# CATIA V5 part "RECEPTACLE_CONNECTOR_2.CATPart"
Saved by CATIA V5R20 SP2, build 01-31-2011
Part number: RECEPTACLE_CONNECTOR_2
Revision: ---
Publications: "MasterKeywayAxis", "InsertFrontFace", "InsertRearFace", "Logical Termination.1", "Logical Pin.1", "CCP", "Face_generated(CCP)", "Face_generated(CCP).1", "BCP", "BCPRPoint_generated(BCP)", "BCPPlane_generated(BCP)", "CaCP", "Face_generated(CaCP)", "Face_generated(CaCP).1", "BaCP", "Face_generated(BaCP)", "Face_generated(BaCP).1", "Axis_generated(CaCP)", "Axis_generated(BaCP)", "Axis_generated(CCP)"
Bounding box of the stored display mesh (mm): x 0 to 34.925, y -14.288 to 14.288, z -14.288 to 14.288
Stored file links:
  C:\Users\ajc8720\Documents\BOEING_WORK\0001-2CES\004-AP242\Boeing-Generic_Harness_R3\RECEPTACLE_CONNECTOR_2.CATPart
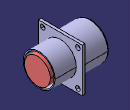
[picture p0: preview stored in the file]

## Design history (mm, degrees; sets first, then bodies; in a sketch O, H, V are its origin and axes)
Parameters
  PartNumber = "RECEPTACLE_CONNECTOR_2"
AxisSystem1 "MasterKeywayAxis": origin (0, 0, 0), X (1, 0, 0), Y (0, 1, 0), Z (0, 0, 1)
Set1 "EGF"
  Set2 "BCP"
    Plane1 "BCPPlane": type Offset, RefPlane face of Pad5, Offset 0, reversed
    Point1 "BCPRPoint": type OnPlane, Support Plane1, H 0, V 0, Direction (0, 1, 0)
  Set3 "BaCP"
    Point2 "BaCPRPoint": (36.0934 {= deleted_ShellLength}, 0, 0)
    Plane2: type OffsetPt, RefPlane yz-plane, RefPoint Point2
  Set4 "CCP"
    Point3 "CCPRPoint": (0, 0, 0)
    Plane3: type OffsetPt, RefPlane yz-plane, RefPoint Point3
  Set5 "CaCP"
    Point4 "CaCPRPoint": type Center, Curve edge [face of Pad1 | face of Pad3]
    Plane4: type OffsetPt, RefPlane yz-plane, RefPoint Point4
Body1 "Shell" (main body)
  Sketch1 on yz-plane, origin (0, 0, 0), H (0, 1, 0), V (0, 0, 1)
    circle A1 centre (0, 0) radius 11.8745
    radius A1 = 11.8745
  Pad1 "ShellFront": profile Sketch1, direction (1, 0, 0), length 18.2372 {= deleted_FlangeFront}
  Sketch2 on zx-plane, origin (0, 0, 0), H (-1, 0, 0), V (0, 0, 1)
    line L1 (0, 11.4046) -> (-0.7874, 11.4046)
    point P2 (-0.7874, 11.4046)
    line L2 (-0.7874, 11.4046) -> (-0.7874, 11.4046)
    line L3 (-0.7874, 11.8745) -> (0, 11.8745)
    line L4 (0, 11.8745) -> (0, 11.4046)
    line L5 (-0.7874, 11.8745) -> (-0.7874, 11.4046)
    point P6 (-0.7874, 11.4046)
    distance H L1 = 11.4046
    length L1 = 0.7874
    distance L3 H = 11.8745
    horizontal: L1 H, L3 H
    vertical: L2 V, L4 V, L5 V
    coincidence: V L4, L5 P2, P6 P2
  Groove1 "ShellFrontRelief": profile Sketch2, axis Sketch2.H, angle 360
  Sketch3 on face of Pad1, origin (18.2372, 0, 0), H (0, 1, 0), V (0, 0, 1)
    circle A1 centre (0, 0) radius 10.4394
    radius A1 = 10.4394
  Pad2 "ShellRear": profile Sketch3, direction (1, 0, 0), length 17.8562 {= deleted_ShellLength - deleted_FlangeFront}
  Sketch4 on zx-plane, origin (0, 0, 0), H (-1, 0, 0), V (0, 0, 1)
    line L1 (-36.0934, 9.1948) -> (-33.8074, 9.1948)
    line L2 (-33.8074, 9.1948) -> (-33.8074, 10.4394)
    line L3 (-33.8074, 10.4394) -> (-36.0934, 10.4394)
    line L4 (-36.0934, 10.4394) -> (-36.0934, 9.1948)
    length L1 = 2.286
    distance V L4 = 36.0934
    distance H L3 = 10.4394
    distance H L1 = 9.1948
    horizontal: L1 H, L3 H
    vertical: L2 V, L4 V
  Groove2 "ShellRearRelief": profile Sketch4, axis Sketch4.H, angle 360
  Sketch5 on yz-plane, origin (0, 0, 0), H (0, 1, 0), V (0, 0, 1)
    line L1 (-14.2875, -14.2875) -> (14.2875, -14.2875)
    line L2 (14.2875, -14.2875) -> (14.2875, 14.2875)
    line L3 (14.2875, 14.2875) -> (-14.2875, 14.2875)
    line L4 (-14.2875, 14.2875) -> (-14.2875, -14.2875)
    circle A1 centre (0, 0) radius 10.4394
    point P5 (10.3837, 12.6287)
    line L5 (10.3837, 12.6287) -> (10.3837, 12.6287)
    point P6 (10.3837, 12.6287)
    arc A2 centre (11.5062, 11.5062) radius 1.5875 from (10.3837, 12.6287) to (12.6287, 10.3837) cw
    point P7 (11.5062, 11.5062)
    point P8 (12.6287, 10.3837)
    line L6 (12.6287, 10.3837) -> (12.6287, 10.3837)
    point P9 (12.6287, 10.3837)
    arc A3 centre (11.5062, 11.5062) radius 1.5875 from (12.6287, 10.3837) to (10.3837, 12.6287) cw
    point P10 (11.5062, 11.5062)
    construction line L7 (0, 0) -> (16.5549, 16.5549)
    point P12 (12.6287, -10.3837)
    point P13 (12.6287, -10.3837)
    line L8 (12.6287, -10.3837) -> (12.6287, -10.3837)
    point P14 (10.3837, -12.6287)
    arc A4 centre (11.5062, -11.5062) radius 1.5875 from (12.6287, -10.3837) to (10.3837, -12.6287) ccw
    point P16 (10.3837, -12.6287)
    line L9 (10.3837, -12.6287) -> (10.3837, -12.6287)
    arc A5 centre (11.5062, -11.5062) radius 1.5875 from (10.3837, -12.6287) to (12.6287, -10.3837) ccw
    point P18 (-12.6287, -10.3837)
    point P19 (-12.6287, -10.3837)
    line L10 (-12.6287, -10.3837) -> (-12.6287, -10.3837)
    point P20 (-10.3837, -12.6287)
    arc A6 centre (-11.5062, -11.5062) radius 1.5875 from (-12.6287, -10.3837) to (-10.3837, -12.6287) cw
    point P22 (-10.3837, -12.6287)
    line L11 (-10.3837, -12.6287) -> (-10.3837, -12.6287)
    arc A7 centre (-11.5062, -11.5062) radius 1.5875 from (-10.3837, -12.6287) to (-12.6287, -10.3837) cw
    point P24 (-10.3837, 12.6287)
    point P25 (-12.6287, 10.3837)
    arc A8 centre (-11.5062, 11.5062) radius 1.5875 from (-12.6287, 10.3837) to (-10.3837, 12.6287) ccw
    point P27 (-10.3837, 12.6287)
    line L12 (-10.3837, 12.6287) -> (-10.3837, 12.6287)
    point P28 (-12.6287, 10.3837)
    arc A9 centre (-11.5062, 11.5062) radius 1.5875 from (-10.3837, 12.6287) to (-12.6287, 10.3837) ccw
    line L13 (-12.6287, 10.3837) -> (-12.6287, 10.3837)
    radius A1 = 10.4394
    length L2 = 28.575
    length L3 = 28.575
    radius A2 = 1.5875
    distance H P7 = 11.5062
    distance H P10 = 11.5062
    angle H L7 = 45
    horizontal: L1 H, L3 H
    vertical: L2 V, L4 V
    symmetry: L2 L4 V, L3 L1 H, L5 L6 L7, P9 P12 H, P8 P13 H, L6 L8 H, P5 P14 H, A3 A4 H, P6 P16 H, L5 L9 H, A2 A5 H, P12 P18 V, P13 P19 V, L8 L10 V, P14 P20 V, A4 A6 V, P16 P22 V, L9 L11 V, A5 A7 V, P5 P24 V, P9 P25 V, A3 A8 V, P6 P27 V, L5 L12 V, P8 P28 V, A2 A9 V, L6 L13 V
    tangency: A2 L5, L6 A2, A3 L5, A3 L6
    coincidence: P7 L7, P10 L7
    parallelism: L6 L7
  Pad3 "MountingFlange": profile Sketch5, direction (1, 0, 0), length 19.9898 {= deleted_FlangeFront + deleted_FlangeThickness}, opposite side length -18.2372 {= -( deleted_FlangeFront )}
  Sketch6 on yz-plane, origin (0, 0, 0), H (0, 1, 0), V (0, 0, 1)
    arc A1 centre (0, 0) radius 9.7663 from (-1.1938, 9.6931) to (1.1938, 9.6931) ccw
    line L1 (1.1938, 9.6931) -> (1.1938, 10.3632)
    line L2 (1.1938, 10.3632) -> (-1.1938, 10.3632)
    line L3 (-1.1938, 10.3632) -> (-1.1938, 9.6931)
    radius A1 = 9.7663
    distance L1 L3 = 2.3876
    distance H L2 = 10.3632
    horizontal: L2 H
    vertical: L1 V, L3 V
    symmetry: L3 L1 V
  Pocket1 "ShellFrontID": profile Sketch6, direction (1, 0, 0), length 13.716 {= deleted_ShellFrontIDLength}
  Sketch7 on face of Pad2, origin (36.0934, 0, 0), H (0, 1, 0), V (0, 0, 1)
    point P1 (0, 0)
    reference intersected line E1 through (0, 0) direction (0, 1) from zx-plane
    reference intersected line E2 through (0, 0) direction (-1, 0) from xy-plane
    coincidence: P1 E1, P1 E2
  Hole1 "ShellRearID": placed by Sketch7, at (36.0934, 0, 0) direction (-1, 0, 0), diameter 19.5326 {= deleted_ShellRearID}, depth 22.3774 {= deleted_ShellLength - deleted_ShellFrontIDLength}
Body2 "Insert"
  Sketch8 on yz-plane, origin (0, 0, 0), H (0, 1, 0), V (0, 0, 1)
    circle A1 centre (0, 0) radius 8.0645
    radius A1 = 8.0645
  Pad4 "FrontInsertPad": profile Sketch8, direction (1, 0, 0), length 22.225 {= deleted_InsertFront + deleted_InsertLength - deleted_GrommetLength}, opposite side length -2.3622 {= -( deleted_InsertFront )}
  Sketch9 on yz-plane, origin (0, 0, 0), H (0, 1, 0), V (0, 0, 1)
    circle A1 centre (0, 0) radius 8.4328
    radius A1 = 8.4328
  Pad5 "RearInsertPad": profile Sketch9, direction (1, 0, 0), length 34.925 {= deleted_InsertFront + deleted_InsertLength}, opposite side length -22.225 {= -( deleted_InsertFront + deleted_InsertLength - deleted_GrommetLength )}
Body3 "CCP"
  Sketch10 on face of Pad1, origin (0, 0, 0), H (0, -1, 0), V (0, 0, 1)
    arc A1 centre (0, 0) radius 1.016 from (-0.672, 0.762) to (0.672, 0.762) ccw
    line L1 (-0.672, 0.762) -> (0.672, 0.762)
    distance L1 H = 0.762
    radius A1 = 1.016
  Sketch11 on face of Pad1, origin (0, 0, 0), H (0, -1, 0), V (0, 0, 1)
    circle A1 centre (0, 0) radius 1.27
    radius A1 = 1.27
  Pad6: profile Sketch11, direction (-1, 0, 0), length 0.254, opposite side length 0.254
  Pocket2: profile Sketch10, direction (-1, 0, 0), through (limit type 6)
Body4 "CaCP"
  Sketch12 on face of Pad3, origin (18.2372, 0, 0), H (0, -1, 0), V (0, 0, 1)
    arc A1 centre (0, 0) radius 1.016 from (-0.672, 0.762) to (0.672, 0.762) ccw
    line L1 (-0.672, 0.762) -> (0.672, 0.762)
    distance L1 H = 0.762
    radius A1 = 1.016
  Pad7: profile Sketch12, direction (1, 0, 0), length 0.508
Body5 "BaCP"
  Sketch13 on face of Pad2, origin (36.0934, 0, 0), H (0, 1, 0), V (0, 0, 1)
    arc A1 centre (0, 0) radius 1.016 from (-0.672, 0.762) to (0.672, 0.762) ccw
    line L1 (-0.672, 0.762) -> (0.672, 0.762)
    distance L1 H = 0.762
    radius A1 = 1.016
  Sketch14 on face of Pad2, origin (36.0934, 0, 0), H (0, 1, 0), V (0, 0, 1)
    circle A1 centre (0, 0) radius 1.27
    radius A1 = 1.27
  Pad8: profile Sketch14, direction (1, 0, 0), length 0.254, opposite side length 0.254
  Pocket3: profile Sketch13, direction (1, 0, 0), through (limit type 6)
